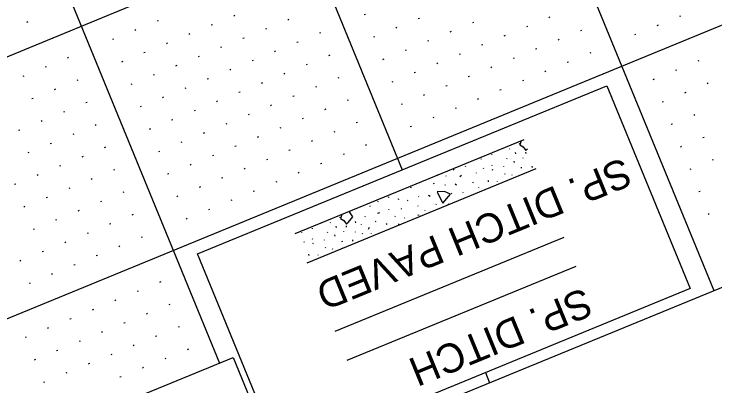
# Model space of a CAD drawing. Extents: x 2148770 to 2150891, y 142633 to 144465.
# Drawn here: x 2149393.1 to 2149537.7, y 143389 to 143465.7 of the extents above; entities that cross this region are included whole.
import ezdxf

# ---------------------------------------------------------------- set-up
doc = ezdxf.new("R2010")
doc.units = 0
for name, color, linetype in [('PR_Grading_Txt', 7, 'Continuous'), ('PR_Misc_Improvement', 7, 'Continuous'), ('PR_Storm_Ditch_Paved', 7, 'Continuous'), ('PR_Storm_Ditch_Special', 7, 'Continuous'), ('SHT_Profile_Grid_Major', 7, 'Continuous'), ('SHT_Profile_Grid_Minor', 7, 'Continuous'), ('SHT_Sheet_Border', 7, 'Continuous')]:
    doc.layers.add(name, color=color, linetype=linetype)

msp = doc.modelspace()

# ---------------------------------------------------------------- linework, layer by layer
at = {"layer": 'PR_Misc_Improvement'}
for points in [[(2149532.57, 143409.09), (2149448.11, 143374.42), (2149430.94, 143416.25), (2149515.39, 143450.93)], [(2149446.89, 143373.92), (2149302.52, 143314.64), (2149293.91, 143335.62), (2149438.28, 143394.89)]]:
    msp.add_lwpolyline(points, close=True, dxfattribs=at)
at = {"layer": 'PR_Storm_Ditch_Paved'}
for p, q in [((2149497.43, 143438.85), (2149497.29, 143438.91)), ((2149493.55, 143437.79), (2149493.55, 143437.82)), ((2149495.3, 143437.86), (2149495.33, 143437.93)), ((2149489.45, 143435.81), (2149489.48, 143435.89)), ((2149491.61, 143436.76), (2149491.55, 143436.61)), ((2149494.74, 143435.91), (2149494.68, 143435.77)), ((2149496.58, 143436.9), (2149496.52, 143437.18)), ((2149498.08, 143435.98), (2149498.11, 143436.05)), ((2149498.69, 143436.94), (2149498.64, 143437.22)), ((2149491.62, 143434.57), (2149491.56, 143434.43)), ((2149496.32, 143435.08), (2149496.27, 143435.36)), ((2149483.88, 143433.53), (2149483.75, 143433.71)), ((2149486.23, 143434.31), (2149486.17, 143434.17)), ((2149488.46, 143432.92), (2149488.48, 143432.99)), ((2149489.93, 143433.94), (2149489.87, 143433.79)), ((2149491.88, 143433.5), (2149491.74, 143433.56)), ((2149494.1, 143434.29), (2149494.13, 143434.36)), ((2149497.83, 143433.99), (2149497.61, 143433.96)), ((2149500, 143434.05), (2149499.94, 143434.32)), ((2149480.56, 143432.4), (2149480.45, 143432.45)), ((2149482.2, 143432.3), (2149482.23, 143432.37)), ((2149485.35, 143432.41), (2149485.06, 143432.12)), ((2149494.31, 143432.78), (2149494.25, 143432.63)), ((2149495.81, 143432.45), (2149495.84, 143432.52)), ((2149497.99, 143432.75), (2149497.93, 143432.61)), ((2149479.77, 143430.59), (2149479.68, 143430.8)), ((2149481.99, 143430.5), (2149481.93, 143430.36)), ((2149484.32, 143430.45), (2149484.08, 143430.59)), ((2149487.75, 143431.03), (2149487.69, 143430.89)), ((2149490.97, 143431.11), (2149490.92, 143431.39)), ((2149492.79, 143431.15), (2149492.82, 143431.22)), ((2149474.93, 143429.97), (2149474.87, 143429.83)), ((2149483.47, 143428.62), (2149483.33, 143428.68)), ((2149485.7, 143428.83), (2149485.72, 143428.9)), ((2149488.94, 143429.87), (2149488.97, 143429.94)), ((2149470.39, 143427.93), (2149470.17, 143427.89)), ((2149472.46, 143427.36), (2149472.4, 143427.63)), ((2149474.36, 143427.19), (2149474.22, 143427.25)), ((2149476.59, 143428.1), (2149476.51, 143428.01)), ((2149478.57, 143428.33), (2149478.92, 143428.18)), ((2149466.61, 143426.02), (2149466.47, 143426.08)), ((2149468.28, 143427), (2149468.14, 143427.06)), ((2149476.43, 143426.09), (2149476.36, 143426.13)), ((2149480.15, 143426.49), (2149480.09, 143426.35)), ((2149482.77, 143426.44), (2149482.62, 143426.5)), ((2149468.13, 143424.63), (2149468.54, 143424.8)), ((2149470.37, 143425.38), (2149470.31, 143425.23)), ((2149473.1, 143425.49), (2149472.96, 143425.55)), ((2149477.86, 143425.14), (2149477.89, 143425.21)), ((2149460.43, 143423.66), (2149460.29, 143423.72)), ((2149463.57, 143422.64), (2149463.51, 143422.91)), ((2149465.51, 143423.97), (2149465.45, 143423.83)), ((2149467.8, 143422.84), (2149467.66, 143422.9)), ((2149471.7, 143424.03), (2149471.64, 143423.88)), ((2149473.65, 143423.59), (2149473.68, 143423.66)), ((2149476.66, 143424.17), (2149476.4, 143424.24)), ((2149454.61, 143421.57), (2149454.55, 143421.42)), ((2149456.55, 143422.6), (2149456.54, 143422.63)), ((2149458.3, 143422.67), (2149458.33, 143422.74)), ((2149459.58, 143421.71), (2149459.52, 143421.99)), ((2149461.69, 143421.75), (2149461.63, 143422.02)), ((2149464.74, 143422.24), (2149464.77, 143422.31)), ((2149466.22, 143421.36), (2149466.42, 143421.74)), ((2149470.04, 143422.28), (2149469.94, 143422.54)), ((2149472.52, 143422.3), (2149472.38, 143422.36)), ((2149452.45, 143420.62), (2149452.48, 143420.69)), ((2149457.74, 143420.72), (2149457.68, 143420.58)), ((2149459.32, 143419.89), (2149459.26, 143420.16)), ((2149461.08, 143420.79), (2149461.11, 143420.86)), ((2149463.52, 143420.73), (2149463.55, 143420.8)), ((2149464.95, 143420.43), (2149464.89, 143420.29)), ((2149466.79, 143420.42), (2149466.82, 143420.49)), ((2149452.93, 143418.75), (2149452.87, 143418.6)), ((2149454.62, 143419.38), (2149454.56, 143419.24)), ((2149457.1, 143419.1), (2149457.13, 143419.17)), ((2149460.83, 143418.8), (2149460.61, 143418.76)), ((2149463, 143418.86), (2149462.94, 143419.13)), ((2149454.88, 143418.31), (2149454.74, 143418.37)), ((2149457.31, 143417.59), (2149457.25, 143417.44)), ((2149458.8, 143417.25), (2149458.83, 143417.33)), ((2149460.99, 143417.56), (2149460.93, 143417.42)), ((2149453.97, 143415.92), (2149453.91, 143416.19)), ((2149455.79, 143415.96), (2149455.82, 143416.03))]:
    msp.add_line(p, q, dxfattribs=at)
for points in [[(2149497.72, 143439.54), (2149497.41, 143438.76), (2149498.11, 143438.3), (2149498.68, 143437.57), (2149498.99, 143437.93)], [(2149480.38, 143429), (2149481.52, 143426.7), (2149483.08, 143428.57), (2149481.86, 143429.12), (2149480.39, 143429.03)], [(2149460.71, 143424.34), (2149460.4, 143423.57), (2149461.1, 143423.11), (2149461.68, 143422.38), (2149461.99, 143422.74)], [(2149461.99, 143422.74), (2149462.99, 143423.91), (2149462.31, 143424.94), (2149462.21, 143424.96)]]:
    msp.add_lwpolyline(points, dxfattribs=at)
at = {"layer": 'PR_Storm_Ditch_Special'}
for p, q in [((2149498.24, 143439.75), (2149450.99, 143420.35)), ((2149500.71, 143433.75), (2149453.46, 143414.35)), ((2149506.5, 143419.63), (2149459.25, 143400.23)), ((2149508.97, 143413.63), (2149461.72, 143394.23))]:
    msp.add_line(p, q, dxfattribs=at)
at = {"layer": 'SHT_Profile_Grid_Major'}
for p, q in [((2150459.23, 143895.22), (2149002.24, 143297.03)), ((2149347.55, 143871.2), (2149537.45, 143408.67)), ((2149301.29, 143852.21), (2149473.16, 143433.59)), ((2150478.22, 143848.96), (2149021.23, 143250.78)), ((2149255.04, 143833.22), (2149435.48, 143393.74)), ((2149490.34, 143391.76), (2149491.19, 143389.68))]:
    msp.add_line(p, q, dxfattribs=at)
at = {"layer": 'SHT_Profile_Grid_Minor'}
for p, q in [((2149438.63, 143465.39), (2149438.39, 143465.29)), ((2149465.55, 143465.63), (2149465.32, 143465.54)), ((2149476.7, 143464.8), (2149476.47, 143464.71)), ((2149503.62, 143465.05), (2149503.39, 143464.95)), ((2149530.55, 143465.29), (2149530.32, 143465.2)), ((2149395.93, 143464.07), (2149395.69, 143463.97)), ((2149422.85, 143464.31), (2149422.62, 143464.22)), ((2149434, 143463.49), (2149433.77, 143463.39)), ((2149449.78, 143464.56), (2149449.54, 143464.46)), ((2149487.85, 143463.98), (2149487.62, 143463.88)), ((2149525.92, 143463.39), (2149525.69, 143463.3)), ((2149418.23, 143462.42), (2149417.99, 143462.32)), ((2149445.15, 143462.66), (2149444.92, 143462.56)), ((2149472.07, 143462.9), (2149471.84, 143462.81)), ((2149483.22, 143462.08), (2149482.99, 143461.98)), ((2149499, 143463.15), (2149498.77, 143463.05)), ((2149510.15, 143462.32), (2149509.92, 143462.23)), ((2149413.6, 143460.52), (2149413.37, 143460.42)), ((2149429.38, 143461.59), (2149429.14, 143461.49)), ((2149440.52, 143460.76), (2149440.29, 143460.67)), ((2149456.3, 143461.83), (2149456.07, 143461.74)), ((2149467.45, 143461), (2149467.22, 143460.91)), ((2149494.37, 143461.25), (2149494.14, 143461.15)), ((2149505.52, 143460.42), (2149505.29, 143460.33)), ((2149521.3, 143461.49), (2149521.07, 143461.4)), ((2149424.75, 143459.69), (2149424.52, 143459.59)), ((2149451.67, 143459.93), (2149451.44, 143459.84)), ((2149478.6, 143460.18), (2149478.37, 143460.08)), ((2149489.75, 143459.35), (2149489.52, 143459.26)), ((2149420.12, 143457.79), (2149419.89, 143457.69)), ((2149435.9, 143458.86), (2149435.67, 143458.77)), ((2149447.05, 143458.03), (2149446.82, 143457.94)), ((2149473.97, 143458.28), (2149473.74, 143458.18)), ((2149500.9, 143458.52), (2149500.67, 143458.43)), ((2149512.05, 143457.7), (2149511.82, 143457.6)), ((2149404.35, 143456.72), (2149404.12, 143456.62)), ((2149431.27, 143456.96), (2149431.04, 143456.87)), ((2149442.42, 143456.14), (2149442.19, 143456.04)), ((2149458.2, 143457.21), (2149457.97, 143457.11)), ((2149469.35, 143456.38), (2149469.12, 143456.28)), ((2149485.12, 143457.45), (2149484.89, 143457.36)), ((2149496.27, 143456.62), (2149496.04, 143456.53)), ((2149399.72, 143454.82), (2149399.49, 143454.72)), ((2149415.5, 143455.89), (2149415.27, 143455.8)), ((2149426.65, 143455.06), (2149426.42, 143454.97)), ((2149453.57, 143455.31), (2149453.34, 143455.21)), ((2149480.5, 143455.55), (2149480.27, 143455.46)), ((2149491.65, 143454.72), (2149491.42, 143454.63)), ((2149507.42, 143455.8), (2149507.19, 143455.7)), ((2149534.35, 143456.04), (2149534.12, 143455.95)), ((2149437.8, 143454.24), (2149437.57, 143454.14)), ((2149448.95, 143453.41), (2149448.72, 143453.31)), ((2149475.87, 143453.65), (2149475.64, 143453.56)), ((2149502.8, 143453.9), (2149502.57, 143453.8)), ((2149529.72, 143454.14), (2149529.49, 143454.05)), ((2149395.1, 143452.92), (2149394.87, 143452.83)), ((2149406.25, 143452.09), (2149406.02, 143452)), ((2149422.02, 143453.16), (2149421.79, 143453.07)), ((2149433.17, 143452.34), (2149432.94, 143452.24)), ((2149460.1, 143452.58), (2149459.87, 143452.49)), ((2149471.25, 143451.75), (2149471.02, 143451.66)), ((2149487.02, 143452.83), (2149486.79, 143452.73)), ((2149498.17, 143452), (2149497.94, 143451.9)), ((2149525.1, 143452.24), (2149524.87, 143452.15)), ((2149417.4, 143451.27), (2149417.17, 143451.17)), ((2149428.55, 143450.44), (2149428.32, 143450.34)), ((2149444.32, 143451.51), (2149444.09, 143451.41)), ((2149455.47, 143450.68), (2149455.24, 143450.59)), ((2149482.4, 143450.93), (2149482.17, 143450.83)), ((2149536.25, 143451.42), (2149536.02, 143451.32)), ((2149401.62, 143450.19), (2149401.39, 143450.1)), ((2149439.7, 143449.61), (2149439.47, 143449.52)), ((2149477.77, 143449.03), (2149477.54, 143448.93)), ((2149493.55, 143450.1), (2149493.32, 143450)), ((2149531.62, 143449.52), (2149531.39, 143449.42)), ((2149397, 143448.29), (2149396.77, 143448.2)), ((2149408.15, 143447.47), (2149407.92, 143447.37)), ((2149423.92, 143448.54), (2149423.69, 143448.44)), ((2149435.07, 143447.71), (2149434.84, 143447.62)), ((2149450.85, 143448.78), (2149450.62, 143448.69)), ((2149462, 143447.96), (2149461.77, 143447.86)), ((2149488.92, 143448.2), (2149488.69, 143448.11)), ((2149527, 143447.62), (2149526.76, 143447.52)), ((2149419.3, 143446.64), (2149419.07, 143446.55)), ((2149446.22, 143446.88), (2149445.99, 143446.79)), ((2149457.37, 143446.06), (2149457.14, 143445.96)), ((2149473.15, 143447.13), (2149472.92, 143447.03)), ((2149484.3, 143446.3), (2149484.06, 143446.21)), ((2149403.52, 143445.57), (2149403.29, 143445.47)), ((2149430.45, 143445.81), (2149430.22, 143445.72)), ((2149441.6, 143444.99), (2149441.37, 143444.89)), ((2149533.52, 143444.89), (2149533.29, 143444.8)), ((2149398.9, 143443.67), (2149398.67, 143443.57)), ((2149425.82, 143443.91), (2149425.59, 143443.82)), ((2149436.97, 143443.09), (2149436.74, 143442.99)), ((2149452.75, 143444.16), (2149452.51, 143444.06)), ((2149463.9, 143443.33), (2149463.66, 143443.24)), ((2149479.67, 143444.4), (2149479.44, 143444.31)), ((2149394.27, 143441.77), (2149394.04, 143441.68)), ((2149410.05, 143442.84), (2149409.82, 143442.75)), ((2149421.2, 143442.01), (2149420.96, 143441.92)), ((2149448.12, 143442.26), (2149447.89, 143442.16)), ((2149475.05, 143442.5), (2149474.81, 143442.41)), ((2149528.89, 143442.99), (2149528.66, 143442.9)), ((2149405.42, 143440.94), (2149405.19, 143440.85)), ((2149432.35, 143441.19), (2149432.11, 143441.09)), ((2149443.5, 143440.36), (2149443.26, 143440.27)), ((2149459.27, 143441.43), (2149459.04, 143441.34)), ((2149535.42, 143440.27), (2149535.19, 143440.17)), ((2149400.8, 143439.04), (2149400.56, 143438.95)), ((2149427.72, 143439.29), (2149427.49, 143439.19)), ((2149454.65, 143439.53), (2149454.41, 143439.44)), ((2149411.95, 143438.22), (2149411.71, 143438.12)), ((2149423.1, 143437.39), (2149422.86, 143437.29)), ((2149438.87, 143438.46), (2149438.64, 143438.37)), ((2149450.02, 143437.63), (2149449.79, 143437.54)), ((2149465.79, 143438.71), (2149465.56, 143438.61)), ((2149530.79, 143438.37), (2149530.56, 143438.27)), ((2149396.17, 143437.15), (2149395.94, 143437.05)), ((2149407.32, 143436.32), (2149407.09, 143436.22)), ((2149434.24, 143436.56), (2149434.01, 143436.47)), ((2149461.17, 143436.81), (2149460.94, 143436.71)), ((2149402.69, 143434.42), (2149402.46, 143434.32)), ((2149429.62, 143434.66), (2149429.39, 143434.57)), ((2149445.39, 143435.73), (2149445.16, 143435.64)), ((2149456.54, 143434.91), (2149456.31, 143434.81)), ((2149537.32, 143435.64), (2149537.09, 143435.55)), ((2149413.84, 143433.59), (2149413.61, 143433.5)), ((2149440.77, 143433.84), (2149440.54, 143433.74)), ((2149451.92, 143433.01), (2149451.69, 143432.91)), ((2149532.69, 143433.74), (2149532.46, 143433.65)), ((2149398.07, 143432.52), (2149397.84, 143432.42)), ((2149409.22, 143431.69), (2149408.99, 143431.6)), ((2149424.99, 143432.76), (2149424.76, 143432.67)), ((2149436.14, 143431.94), (2149435.91, 143431.84)), ((2149393.44, 143430.62), (2149393.21, 143430.53)), ((2149447.29, 143431.11), (2149447.06, 143431.01)), ((2149404.59, 143429.79), (2149404.36, 143429.7)), ((2149415.74, 143428.97), (2149415.51, 143428.87)), ((2149431.52, 143430.04), (2149431.29, 143429.94)), ((2149442.67, 143429.21), (2149442.44, 143429.12)), ((2149534.59, 143429.12), (2149534.36, 143429.02)), ((2149399.97, 143427.89), (2149399.74, 143427.8)), ((2149426.89, 143428.14), (2149426.66, 143428.04)), ((2149438.04, 143427.31), (2149437.81, 143427.22)), ((2149395.34, 143426), (2149395.11, 143425.9)), ((2149411.12, 143427.07), (2149410.89, 143426.97)), ((2149406.49, 143425.17), (2149406.26, 143425.07)), ((2149417.64, 143424.34), (2149417.41, 143424.25)), ((2149433.42, 143425.41), (2149433.19, 143425.32)), ((2149536.49, 143424.49), (2149536.26, 143424.4)), ((2149401.87, 143423.27), (2149401.64, 143423.17)), ((2149428.79, 143423.51), (2149428.56, 143423.42)), ((2149397.24, 143421.37), (2149397.01, 143421.28)), ((2149413.02, 143422.44), (2149412.79, 143422.35)), ((2149408.39, 143420.54), (2149408.16, 143420.45)), ((2149403.77, 143418.64), (2149403.54, 143418.55)), ((2149419.54, 143419.72), (2149419.31, 143419.62)), ((2149414.92, 143417.82), (2149414.68, 143417.72)), ((2149399.14, 143416.74), (2149398.91, 143416.65)), ((2149410.29, 143415.92), (2149410.06, 143415.82)), ((2149394.52, 143414.85), (2149394.28, 143414.75)), ((2149405.67, 143414.02), (2149405.43, 143413.92)), ((2149401.04, 143412.12), (2149400.81, 143412.02)), ((2149396.41, 143410.22), (2149396.18, 143410.13)), ((2149423.34, 143410.46), (2149423.11, 143410.37)), ((2149418.71, 143408.57), (2149418.48, 143408.47)), ((2149414.09, 143406.67), (2149413.86, 143406.57)), ((2149425.24, 143405.84), (2149425.01, 143405.74)), ((2149409.46, 143404.77), (2149409.23, 143404.67)), ((2149404.84, 143402.87), (2149404.61, 143402.77)), ((2149420.61, 143403.94), (2149420.38, 143403.85)), ((2149415.99, 143402.04), (2149415.76, 143401.95)), ((2149427.14, 143401.21), (2149426.91, 143401.12)), ((2149400.21, 143400.97), (2149399.98, 143400.87)), ((2149411.36, 143400.14), (2149411.13, 143400.05)), ((2149395.59, 143399.07), (2149395.36, 143398.98)), ((2149406.74, 143398.24), (2149406.51, 143398.15)), ((2149422.51, 143399.31), (2149422.28, 143399.22)), ((2149417.89, 143397.42), (2149417.66, 143397.32)), ((2149402.11, 143396.34), (2149401.88, 143396.25)), ((2149413.26, 143395.52), (2149413.03, 143395.42)), ((2149429.04, 143396.59), (2149428.81, 143396.49)), ((2149397.49, 143394.45), (2149397.26, 143394.35)), ((2149424.41, 143394.69), (2149424.18, 143394.59)), ((2149408.64, 143393.62), (2149408.4, 143393.52)), ((2149419.79, 143392.79), (2149419.55, 143392.7)), ((2149404.01, 143391.72), (2149403.78, 143391.62)), ((2149399.39, 143389.82), (2149399.15, 143389.72)), ((2149415.16, 143390.89), (2149414.93, 143390.8))]:
    msp.add_line(p, q, dxfattribs=at)
at = {"layer": 'SHT_Sheet_Border'}
msp.add_line((2150497.21, 143802.71), (2149040.22, 143204.53), dxfattribs=at)

# ---------------------------------------------------------------- texts
at = {"layer": 'PR_Grading_Txt'}
for s, p in [('SP. DITCH PAVED', (2149518.82, 143436.23)), ('SP. DITCH', (2149510.72, 143409.4))]:
    msp.add_text(s, height=6, rotation=202.3213, dxfattribs=at).set_placement(p)

doc.saveas('drawing.dxf')
